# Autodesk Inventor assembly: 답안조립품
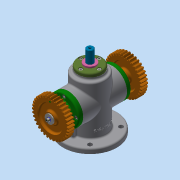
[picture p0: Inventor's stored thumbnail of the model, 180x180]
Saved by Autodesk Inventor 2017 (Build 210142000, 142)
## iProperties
Part Number: 답안조립품
Material: 일반
Document SubType Name: Assembly
Designer: mrc
Author: mrc
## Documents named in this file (17)
- C:\Users\mrc\Desktop\600606V1009\답안조립품.iam
- C:\Users\mrc\Desktop\600606V1009\본체.ipt
- C:\Users\mrc\Desktop\600606V1009\가변스프링.ipt
- C:\Users\mrc\Desktop\600606V1009\멈춤링.ipt
- C:\Users\mrc\Desktop\600606V1009\베어링 6203.ipt
- C:\Users\mrc\Desktop\600606V1009\볼트 M4.ipt
- C:\Users\mrc\Desktop\600606V1009\부시.ipt
- C:\Users\mrc\Desktop\600606V1009\스퍼기어.ipt
- C:\Users\mrc\Desktop\600606V1009\스프링와셔.ipt
- C:\Users\mrc\Desktop\600606V1009\스프링조립용 와셔.ipt
- C:\Users\mrc\Desktop\600606V1009\슬라이더.ipt
- C:\Users\mrc\Desktop\600606V1009\오일 실 17 30 8.ipt
- C:\Users\mrc\Desktop\600606V1009\커버 A.ipt
- C:\Users\mrc\Desktop\600606V1009\커버 B.ipt
- C:\Users\mrc\Desktop\600606V1009\키 4x4x12.ipt
- C:\Users\mrc\Desktop\600606V1009\편심축.ipt
- C:\Users\mrc\Desktop\600606V1009\평와셔.ipt
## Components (1 placed, 1 different names)
1. 가변스프링:1
